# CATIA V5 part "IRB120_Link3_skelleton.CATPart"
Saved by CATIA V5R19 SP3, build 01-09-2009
Part number: IRB120_Link3_skelleton
Bounding box of the stored display mesh (mm): x 0 to 302, y -65 to 0, z 0 to 70
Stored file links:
  Z:\Projects\ABB_Robotics\ABB LIB\V5\V5PARTS\ABB\120\IRB120_Link3_skelleton.CATPart
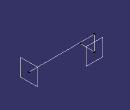
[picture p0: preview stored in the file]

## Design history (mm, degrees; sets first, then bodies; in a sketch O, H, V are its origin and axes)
Body1 (main body)
  Line1: type PtPt, FirstPoint {point type Coord, X 0, Y 0, Z 0}, SecondPoint {point type Coord, X 0, Y 0, Z 70, RefPoint {point type Coord, X 0, Y 0, Z 0}}
  Line2: type PtPt, FirstPoint vertex of Line1, SecondPoint {point type Coord, X 0, Y -65, Z 0, RefPoint vertex of Line1}
  Line3: type PtPt, FirstPoint vertex of Line1, SecondPoint {point type Coord, X 302, Y 0, Z 0, RefPoint vertex of Line1}
  Plane1: type OffsetPt, RefPlane yz-plane, RefPoint vertex of Line3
